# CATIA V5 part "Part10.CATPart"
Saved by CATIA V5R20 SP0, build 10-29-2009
Part number: 9SA120014-C_acabado
Revision: ANY
Definition: UNKNOWN
Nomenclature: 9SA120014-C_acabado
Source: Unknown
Bounding box of the stored display mesh (mm): x -5.85 to 5.85, y 0 to 14, z -6 to 6
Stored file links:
  C:\Users\Utente\Desktop\IO LAVORO\3D X SITO CF\CUMSA\3D files SA\SA 120314\Part10.CATPart
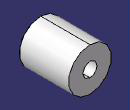
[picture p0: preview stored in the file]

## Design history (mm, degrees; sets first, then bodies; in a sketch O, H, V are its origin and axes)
Body1 "Envolver1" (main body)
  Solid1: solid without history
